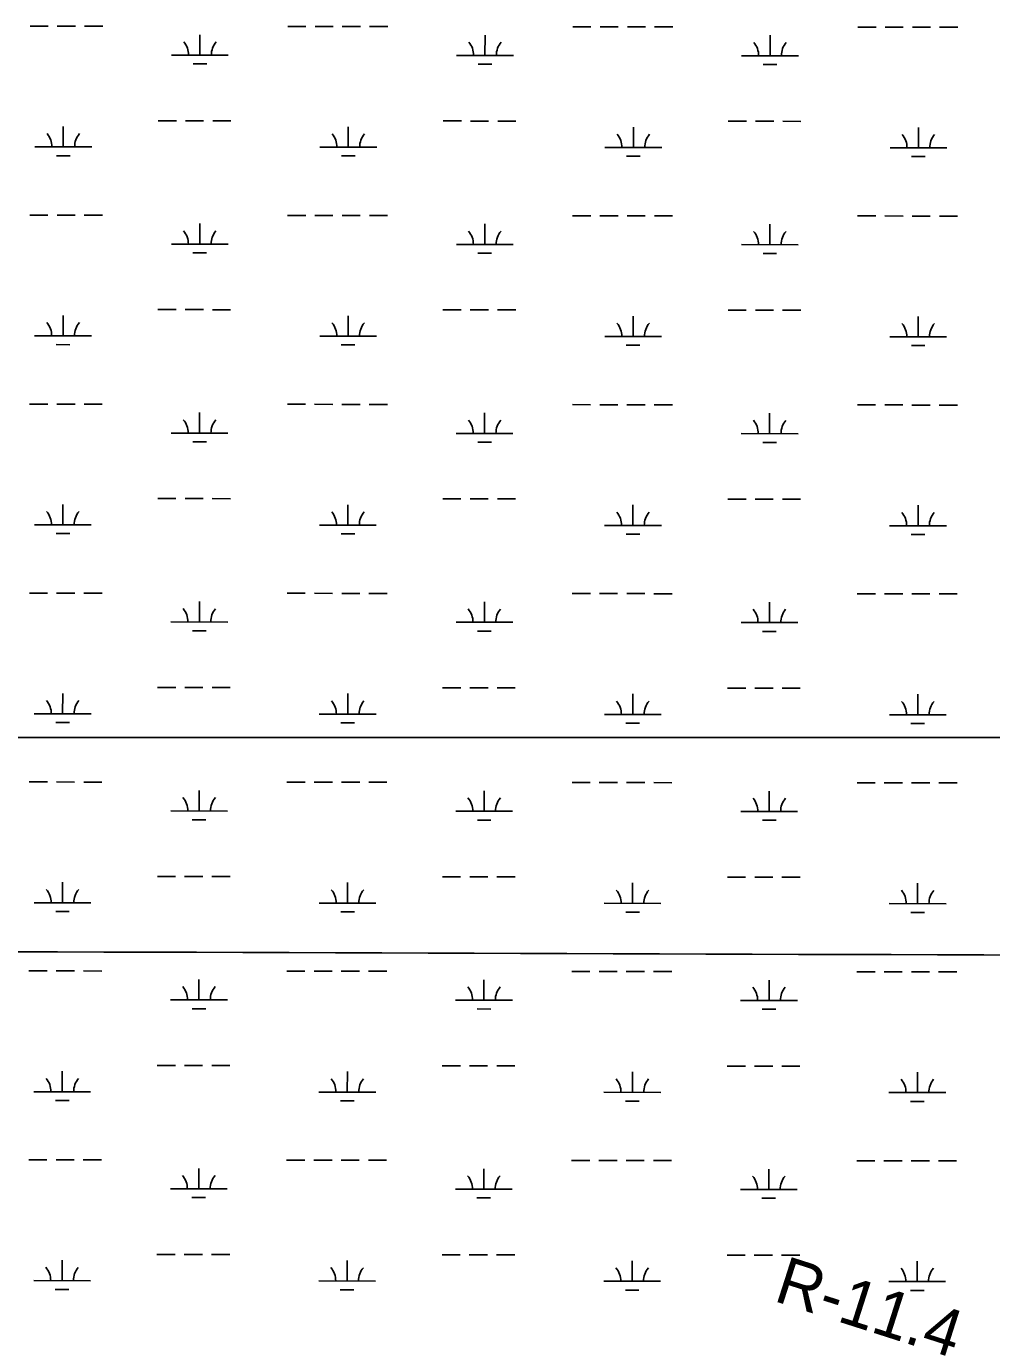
# Model space of a CAD drawing. Extents: x 3148686 to 3186545, y 916144 to 941516.
# Drawn here: x 3158945 to 3160645, y 932988 to 935288 of the extents above; entities that cross this region are included whole.
import ezdxf

# ---------------------------------------------------------------- set-up
doc = ezdxf.new("R2010")
doc.units = 0
for name, color, linetype in [('V-GRID-MAJR', 7, 'Continuous'), ('V-RIVR-RANG-IDEN', 7, 'Continuous'), ('V-SITE-VEGE', 7, 'Continuous'), ('V-WETL-SWMP', 7, 'Continuous')]:
    doc.layers.add(name, color=color, linetype=linetype)

msp = doc.modelspace()

# ---------------------------------------------------------------- linework, layer by layer
at = {"layer": 'V-GRID-MAJR'}
msp.add_spline([(3152965.6, 933679.7), (3155575.1, 933670.5), (3160794.2, 933652.6), (3166013.2, 933635.6), (3171232.3, 933619.2), (3176451.4, 933603.7), (3181670.5, 933588.9), (3184280, 933581.8)], degree=3, dxfattribs=at)
at = {"layer": 'V-SITE-VEGE'}
for p, q in [((3161771.7, 934035.8), (3157650.8, 934035.8)), ((3158561.4, 934035.8), (3161771.7, 934035.8))]:
    msp.add_line(p, q, dxfattribs=at)
at = {"layer": 'V-WETL-SWMP'}
for p, q in [((3158951.7, 935288.4), (3158983.7, 935288.4)), ((3158999.7, 935288.4), (3159031.7, 935288.3)), ((3159047.7, 935288.3), (3159079.7, 935288.3)), ((3159405.6, 935288), (3159437.6, 935287.9)), ((3159453.6, 935287.9), (3159485.6, 935287.9)), ((3159501.6, 935287.9), (3159533.6, 935287.8)), ((3159549.6, 935287.8), (3159581.6, 935287.8)), ((3159907.5, 935287.4), (3159939.5, 935287.4)), ((3159955.5, 935287.4), (3159987.5, 935287.3)), ((3160003.5, 935287.3), (3160035.5, 935287.3)), ((3160051.5, 935287.3), (3160083.5, 935287.2)), ((3160409.4, 935286.9), (3160441.4, 935286.9)), ((3160457.4, 935286.8), (3160489.4, 935286.8)), ((3160505.4, 935286.8), (3160537.4, 935286.8)), ((3160553.4, 935286.7), (3160585.4, 935286.7)), ((3159250.9, 935237.4), (3159251, 935273.4)), ((3159752.8, 935236.8), (3159752.9, 935272.8)), ((3160254.7, 935236.3), (3160254.8, 935272.3)), ((3159200.9, 935237.4), (3159300.9, 935237.3)), ((3159702.8, 935236.9), (3159802.8, 935236.8)), ((3160204.7, 935236.4), (3160304.7, 935236.3)), ((3159238.9, 935222), (3159262.9, 935221.9)), ((3159740.8, 935221.4), (3159764.8, 935221.4)), ((3160242.7, 935220.9), (3160266.7, 935220.9)), ((3159177.4, 935122), (3159209.4, 935122)), ((3159225.4, 935122), (3159257.4, 935121.9)), ((3159273.4, 935121.9), (3159305.4, 935121.9)), ((3159679.3, 935121.5), (3159711.3, 935121.5)), ((3159727.3, 935121.4), (3159759.3, 935121.4)), ((3159775.3, 935121.4), (3159807.3, 935121.4)), ((3160181.2, 935121), (3160213.2, 935120.9)), ((3160229.2, 935120.9), (3160261.2, 935120.9)), ((3160277.2, 935120.9), (3160309.2, 935120.8)), ((3159010.3, 935075.8), (3159010.3, 935111.8)), ((3159512.2, 935075.2), (3159512.2, 935111.2)), ((3160014.1, 935074.7), (3160014.1, 935110.7)), ((3160516, 935074.2), (3160516, 935110.2)), ((3158960.3, 935075.8), (3159060.3, 935075.7)), ((3159462.2, 935075.3), (3159562.2, 935075.2)), ((3159964.1, 935074.8), (3160064.1, 935074.7)), ((3160466, 935074.2), (3160566, 935074.1)), ((3158998.3, 935060.3), (3159022.3, 935060.3)), ((3159500.2, 935059.8), (3159524.2, 935059.8)), ((3160002.1, 935059.3), (3160026.1, 935059.3)), ((3160504, 935058.8), (3160528, 935058.7)), ((3158951.3, 934955.8), (3158983.3, 934955.7)), ((3158999.3, 934955.7), (3159031.3, 934955.7)), ((3159047.3, 934955.7), (3159079.3, 934955.6)), ((3159250.6, 934904.7), (3159250.6, 934940.7)), ((3159405.2, 934955.3), (3159437.2, 934955.2)), ((3159453.2, 934955.2), (3159485.2, 934955.2)), ((3159501.2, 934955.2), (3159533.2, 934955.1)), ((3159549.2, 934955.1), (3159581.2, 934955.1)), ((3159752.5, 934904.2), (3159752.5, 934940.2)), ((3159907.1, 934954.7), (3159939.1, 934954.7)), ((3159955.1, 934954.7), (3159987.1, 934954.7)), ((3160003.1, 934954.6), (3160035.1, 934954.6)), ((3160051.1, 934954.6), (3160083.1, 934954.6)), ((3160254.4, 934903.6), (3160254.4, 934939.6)), ((3160409, 934954.2), (3160441, 934954.2)), ((3160457, 934954.2), (3160489, 934954.1)), ((3160505, 934954.1), (3160537, 934954.1)), ((3160553, 934954.1), (3160585, 934954)), ((3159200.6, 934904.8), (3159300.6, 934904.6)), ((3159702.5, 934904.2), (3159802.5, 934904.1)), ((3160204.4, 934903.7), (3160304.4, 934903.6)), ((3159238.5, 934889.3), (3159262.5, 934889.3)), ((3159740.5, 934888.8), (3159764.5, 934888.7)), ((3160242.4, 934888.2), (3160266.4, 934888.2)), ((3159009.9, 934743.1), (3159010, 934779.1)), ((3159177, 934789.3), (3159209, 934789.3)), ((3159225, 934789.3), (3159257, 934789.3)), ((3159273, 934789.2), (3159305, 934789.2)), ((3159511.8, 934742.6), (3159511.9, 934778.6)), ((3159678.9, 934788.8), (3159710.9, 934788.8)), ((3159726.9, 934788.8), (3159758.9, 934788.7)), ((3159774.9, 934788.7), (3159806.9, 934788.7)), ((3160013.7, 934742), (3160013.8, 934778)), ((3160180.9, 934788.3), (3160212.9, 934788.3)), ((3160228.9, 934788.2), (3160260.9, 934788.2)), ((3160276.9, 934788.2), (3160308.9, 934788.2)), ((3160515.6, 934741.5), (3160515.7, 934777.5)), ((3158959.9, 934743.1), (3159059.9, 934743)), ((3159461.8, 934742.6), (3159561.8, 934742.5)), ((3159963.7, 934742.1), (3160063.7, 934742)), ((3160465.6, 934741.6), (3160565.6, 934741.5)), ((3158997.9, 934727.7), (3159021.9, 934727.6)), ((3159499.8, 934727.1), (3159523.8, 934727.1)), ((3160001.7, 934726.6), (3160025.7, 934726.6)), ((3160503.6, 934726.1), (3160527.6, 934726.1)), ((3158951, 934623.1), (3158983, 934623)), ((3158999, 934623), (3159031, 934623)), ((3159047, 934623), (3159079, 934622.9)), ((3159404.9, 934622.6), (3159436.9, 934622.6)), ((3159452.9, 934622.6), (3159484.9, 934622.5)), ((3159500.9, 934622.5), (3159532.9, 934622.5)), ((3159548.9, 934622.5), (3159580.9, 934622.4)), ((3159906.8, 934622.1), (3159938.8, 934622)), ((3159954.8, 934622), (3159986.8, 934622)), ((3160002.8, 934622), (3160034.8, 934621.9)), ((3160050.8, 934621.9), (3160082.8, 934621.9)), ((3160408.7, 934621.5), (3160440.7, 934621.5)), ((3160456.7, 934621.5), (3160488.7, 934621.5)), ((3160504.7, 934621.4), (3160536.7, 934621.4)), ((3160552.7, 934621.4), (3160584.7, 934621.4)), ((3159250.2, 934572), (3159250.3, 934608)), ((3159752.1, 934571.5), (3159752.2, 934607.5)), ((3160254, 934571), (3160254.1, 934607)), ((3159200.2, 934572.1), (3159300.2, 934572)), ((3159702.1, 934571.5), (3159802.1, 934571.4)), ((3160204, 934571), (3160304, 934570.9)), ((3159238.2, 934556.6), (3159262.2, 934556.6)), ((3159740.1, 934556.1), (3159764.1, 934556.1)), ((3160242, 934555.5), (3160266, 934555.5)), ((3159176.7, 934456.7), (3159208.7, 934456.6)), ((3159224.7, 934456.6), (3159256.7, 934456.6)), ((3159272.7, 934456.6), (3159304.7, 934456.5)), ((3159678.6, 934456.1), (3159710.6, 934456.1)), ((3159726.6, 934456.1), (3159758.6, 934456.1)), ((3159774.6, 934456), (3159806.6, 934456)), ((3160180.5, 934455.6), (3160212.5, 934455.6)), ((3160228.5, 934455.6), (3160260.5, 934455.5)), ((3160276.5, 934455.5), (3160308.5, 934455.5)), ((3159009.6, 934410.4), (3159009.6, 934446.4)), ((3159511.5, 934409.9), (3159511.5, 934445.9)), ((3160013.4, 934409.4), (3160013.4, 934445.4)), ((3160515.3, 934408.8), (3160515.3, 934444.8)), ((3158959.6, 934410.5), (3159059.6, 934410.4)), ((3159461.5, 934409.9), (3159561.5, 934409.8)), ((3159963.4, 934409.4), (3160063.4, 934409.3)), ((3160465.3, 934408.9), (3160565.3, 934408.8)), ((3158997.6, 934395), (3159021.6, 934395)), ((3159499.5, 934394.5), (3159523.5, 934394.4)), ((3160001.4, 934393.9), (3160025.4, 934393.9)), ((3160503.3, 934393.4), (3160527.3, 934393.4)), ((3158950.6, 934290.4), (3158982.6, 934290.4)), ((3158998.6, 934290.4), (3159030.6, 934290.3)), ((3159046.6, 934290.3), (3159078.6, 934290.3)), ((3159249.9, 934239.3), (3159249.9, 934275.3)), ((3159404.5, 934289.9), (3159436.5, 934289.9)), ((3159452.5, 934289.9), (3159484.5, 934289.8)), ((3159500.5, 934289.8), (3159532.5, 934289.8)), ((3159548.5, 934289.8), (3159580.5, 934289.7)), ((3159751.8, 934238.8), (3159751.8, 934274.8)), ((3159906.4, 934289.4), (3159938.4, 934289.4)), ((3159954.4, 934289.3), (3159986.4, 934289.3)), ((3160002.4, 934289.3), (3160034.4, 934289.3)), ((3160050.4, 934289.2), (3160082.4, 934289.2)), ((3160253.7, 934238.3), (3160253.7, 934274.3)), ((3160408.3, 934288.9), (3160440.3, 934288.8)), ((3160456.3, 934288.8), (3160488.3, 934288.8)), ((3160504.3, 934288.8), (3160536.3, 934288.7)), ((3160552.3, 934288.7), (3160584.3, 934288.7)), ((3159199.9, 934239.4), (3159299.9, 934239.3)), ((3159237.8, 934223.9), (3159261.8, 934223.9)), ((3159701.8, 934238.9), (3159801.8, 934238.8)), ((3159739.8, 934223.4), (3159763.8, 934223.4)), ((3160203.7, 934238.3), (3160303.7, 934238.2)), ((3160241.7, 934222.9), (3160265.7, 934222.8)), ((3159009.2, 934077.7), (3159009.3, 934113.7)), ((3159176.3, 934124), (3159208.3, 934124)), ((3159224.3, 934123.9), (3159256.3, 934123.9)), ((3159272.3, 934123.9), (3159304.3, 934123.9)), ((3159511.1, 934077.2), (3159511.2, 934113.2)), ((3159678.2, 934123.5), (3159710.2, 934123.4)), ((3159726.2, 934123.4), (3159758.2, 934123.4)), ((3159774.2, 934123.4), (3159806.2, 934123.3)), ((3160013, 934076.7), (3160013.1, 934112.7)), ((3160180.1, 934122.9), (3160212.1, 934122.9)), ((3160228.1, 934122.9), (3160260.1, 934122.9)), ((3160276.1, 934122.8), (3160308.1, 934122.8)), ((3160514.9, 934076.2), (3160515, 934112.2)), ((3158959.2, 934077.8), (3159059.2, 934077.7)), ((3158997.2, 934062.3), (3159021.2, 934062.3)), ((3159461.1, 934077.3), (3159561.1, 934077.2)), ((3159499.1, 934061.8), (3159523.1, 934061.8)), ((3159963, 934076.7), (3160063, 934076.6)), ((3160001, 934061.3), (3160025, 934061.2)), ((3160464.9, 934076.2), (3160564.9, 934076.1)), ((3160502.9, 934060.7), (3160526.9, 934060.7)), ((3158950.3, 933957.7), (3158982.3, 933957.7)), ((3158998.3, 933957.7), (3159030.3, 933957.6)), ((3159046.3, 933957.6), (3159078.3, 933957.6)), ((3159404.2, 933957.3), (3159436.2, 933957.2)), ((3159452.2, 933957.2), (3159484.2, 933957.2)), ((3159500.2, 933957.2), (3159532.2, 933957.1)), ((3159548.2, 933957.1), (3159580.2, 933957.1)), ((3159906.1, 933956.7), (3159938.1, 933956.7)), ((3159954.1, 933956.7), (3159986.1, 933956.6)), ((3160002.1, 933956.6), (3160034.1, 933956.6)), ((3160050.1, 933956.6), (3160082.1, 933956.5)), ((3160408, 933956.2), (3160440, 933956.2)), ((3160456, 933956.1), (3160488, 933956.1)), ((3160504, 933956.1), (3160536, 933956.1)), ((3160552, 933956), (3160584, 933956)), ((3159249.5, 933906.7), (3159249.6, 933942.7)), ((3159751.4, 933906.1), (3159751.5, 933942.1)), ((3160253.3, 933905.6), (3160253.4, 933941.6)), ((3159199.5, 933906.7), (3159299.5, 933906.6)), ((3159701.4, 933906.2), (3159801.4, 933906.1)), ((3160203.3, 933905.7), (3160303.3, 933905.6)), ((3159237.5, 933891.3), (3159261.5, 933891.2)), ((3159739.4, 933890.7), (3159763.4, 933890.7)), ((3160241.3, 933890.2), (3160265.3, 933890.2)), ((3159176, 933791.3), (3159208, 933791.3)), ((3159224, 933791.3), (3159256, 933791.2)), ((3159272, 933791.2), (3159304, 933791.2)), ((3159677.9, 933790.8), (3159709.9, 933790.8)), ((3159725.9, 933790.7), (3159757.9, 933790.7)), ((3159773.9, 933790.7), (3159805.9, 933790.7)), ((3160179.8, 933790.3), (3160211.8, 933790.2)), ((3160227.8, 933790.2), (3160259.8, 933790.2)), ((3160275.8, 933790.2), (3160307.8, 933790.1)), ((3159008.9, 933745.1), (3159008.9, 933781.1)), ((3159510.8, 933744.5), (3159510.8, 933780.5)), ((3160012.7, 933744), (3160012.7, 933780)), ((3160514.6, 933743.5), (3160514.6, 933779.5)), ((3158958.9, 933745.1), (3159058.9, 933745)), ((3159460.8, 933744.6), (3159560.8, 933744.5)), ((3159962.7, 933744.1), (3160062.7, 933744)), ((3160464.6, 933743.5), (3160564.6, 933743.4)), ((3158996.9, 933729.6), (3159020.9, 933729.6)), ((3159498.8, 933729.1), (3159522.8, 933729.1)), ((3160000.7, 933728.6), (3160024.7, 933728.6)), ((3160502.6, 933728.1), (3160526.6, 933728)), ((3158949.9, 933625.1), (3158981.9, 933625)), ((3158997.9, 933625), (3159029.9, 933625)), ((3159045.9, 933625), (3159077.9, 933624.9)), ((3159403.8, 933624.6), (3159435.8, 933624.5)), ((3159451.8, 933624.5), (3159483.8, 933624.5)), ((3159499.8, 933624.5), (3159531.8, 933624.4)), ((3159547.8, 933624.4), (3159579.8, 933624.4)), ((3159905.7, 933624.1), (3159937.7, 933624)), ((3159249.2, 933574), (3159249.2, 933610)), ((3159751.1, 933573.5), (3159751.1, 933609.5)), ((3159953.7, 933624), (3159985.7, 933624)), ((3160001.7, 933623.9), (3160033.7, 933623.9)), ((3160049.7, 933623.9), (3160081.7, 933623.9)), ((3160253, 933572.9), (3160253, 933608.9)), ((3160407.6, 933623.5), (3160439.6, 933623.5)), ((3160455.6, 933623.5), (3160487.6, 933623.4)), ((3160503.6, 933623.4), (3160535.6, 933623.4)), ((3160551.6, 933623.4), (3160583.6, 933623.3)), ((3159199.2, 933574.1), (3159299.2, 933573.9)), ((3159237.1, 933558.6), (3159261.1, 933558.6)), ((3159701.1, 933573.5), (3159801.1, 933573.4)), ((3159739.1, 933558.1), (3159763.1, 933558)), ((3160203, 933573), (3160303, 933572.9)), ((3160241, 933557.5), (3160265, 933557.5)), ((3159008.5, 933412.4), (3159008.6, 933448.4)), ((3159175.6, 933458.6), (3159207.6, 933458.6)), ((3159223.6, 933458.6), (3159255.6, 933458.6)), ((3159271.6, 933458.5), (3159303.6, 933458.5)), ((3159510.4, 933411.9), (3159510.5, 933447.9)), ((3159677.5, 933458.1), (3159709.5, 933458.1)), ((3159725.5, 933458.1), (3159757.5, 933458)), ((3159773.5, 933458), (3159805.5, 933458)), ((3160012.3, 933411.3), (3160012.4, 933447.3)), ((3160179.4, 933457.6), (3160211.4, 933457.6)), ((3160227.4, 933457.5), (3160259.4, 933457.5)), ((3160275.4, 933457.5), (3160307.4, 933457.5)), ((3160514.2, 933410.8), (3160514.3, 933446.8)), ((3158958.5, 933412.4), (3159058.5, 933412.3)), ((3158996.5, 933397), (3159020.5, 933396.9)), ((3159460.4, 933411.9), (3159560.4, 933411.8)), ((3159498.4, 933396.4), (3159522.4, 933396.4)), ((3159962.3, 933411.4), (3160062.3, 933411.3)), ((3160000.3, 933395.9), (3160024.3, 933395.9)), ((3160464.2, 933410.9), (3160564.2, 933410.8)), ((3160502.2, 933395.4), (3160526.2, 933395.4)), ((3158949.6, 933292.4), (3158981.6, 933292.3)), ((3158997.6, 933292.3), (3159029.6, 933292.3)), ((3159045.6, 933292.3), (3159077.6, 933292.2)), ((3159403.5, 933291.9), (3159435.5, 933291.9)), ((3159451.5, 933291.9), (3159483.5, 933291.8)), ((3159499.5, 933291.8), (3159531.5, 933291.8)), ((3159547.5, 933291.8), (3159579.5, 933291.7)), ((3159905.4, 933291.4), (3159937.4, 933291.3)), ((3159953.4, 933291.3), (3159985.4, 933291.3)), ((3160001.4, 933291.3), (3160033.4, 933291.2)), ((3160049.4, 933291.2), (3160081.4, 933291.2)), ((3160407.3, 933290.8), (3160439.3, 933290.8)), ((3160455.3, 933290.8), (3160487.3, 933290.8)), ((3160503.3, 933290.7), (3160535.3, 933290.7)), ((3160551.3, 933290.7), (3160583.3, 933290.7)), ((3159248.8, 933241.3), (3159248.9, 933277.3)), ((3159750.7, 933240.8), (3159750.8, 933276.8)), ((3160252.6, 933240.3), (3160252.7, 933276.3)), ((3159198.8, 933241.4), (3159298.8, 933241.3)), ((3159700.7, 933240.8), (3159800.7, 933240.7)), ((3160202.6, 933240.3), (3160302.6, 933240.2)), ((3159236.8, 933225.9), (3159260.8, 933225.9)), ((3159738.7, 933225.4), (3159762.7, 933225.4)), ((3160240.6, 933224.8), (3160264.6, 933224.8)), ((3159175.3, 933126), (3159207.3, 933125.9)), ((3159223.3, 933125.9), (3159255.3, 933125.9)), ((3159271.3, 933125.9), (3159303.3, 933125.8)), ((3159677.2, 933125.4), (3159709.2, 933125.4)), ((3159725.2, 933125.4), (3159757.2, 933125.4)), ((3159773.2, 933125.3), (3159805.2, 933125.3)), ((3160179.1, 933124.9), (3160211.1, 933124.9)), ((3160227.1, 933124.9), (3160259.1, 933124.8)), ((3160275.1, 933124.8), (3160307.1, 933124.8)), ((3159008.2, 933079.7), (3159008.2, 933115.7)), ((3159510.1, 933079.2), (3159510.1, 933115.2)), ((3160012, 933078.7), (3160012, 933114.7)), ((3160513.9, 933078.1), (3160513.9, 933114.1)), ((3158958.2, 933079.8), (3159058.2, 933079.7)), ((3159460.1, 933079.2), (3159560.1, 933079.1)), ((3159962, 933078.7), (3160062, 933078.6)), ((3160463.9, 933078.2), (3160563.9, 933078.1)), ((3158996.2, 933064.3), (3159020.2, 933064.3)), ((3159498.1, 933063.8), (3159522.1, 933063.7)), ((3160000, 933063.2), (3160024, 933063.2)), ((3160501.9, 933062.7), (3160525.9, 933062.7))]:
    msp.add_line(p, q, dxfattribs=at)
for centre, start, end in [((3159195.7, 935237.9), 359.1678, 40.7115), ((3159306.2, 935237.8), 139.1678, 180.7115), ((3159697.6, 935237.4), 359.1678, 40.7115), ((3159808.1, 935237.3), 139.1678, 180.7115), ((3160199.5, 935236.8), 359.1678, 40.7115), ((3160310, 935236.7), 139.1678, 180.7115), ((3158955, 935076.3), 359.1678, 40.7115), ((3159065.5, 935076.2), 139.1678, 180.7115), ((3159456.9, 935075.8), 359.1678, 40.7115), ((3159567.4, 935075.7), 139.1678, 180.7115), ((3159958.8, 935075.2), 359.1678, 40.7115), ((3160069.3, 935075.1), 139.1678, 180.7115), ((3160460.8, 935074.7), 359.1678, 40.7115), ((3160571.2, 935074.6), 139.1678, 180.7115), ((3159195.3, 934905.2), 359.1678, 40.7115), ((3159305.8, 934905.1), 139.1678, 180.7115), ((3159697.2, 934904.7), 359.1678, 40.7115), ((3159807.7, 934904.6), 139.1678, 180.7115), ((3160199.1, 934904.2), 359.1678, 40.7115), ((3160309.6, 934904.1), 139.1678, 180.7115), ((3158954.7, 934743.6), 359.1678, 40.7115), ((3159065.2, 934743.5), 139.1678, 180.7115), ((3159456.6, 934743.1), 359.1678, 40.7115), ((3159567.1, 934743), 139.1678, 180.7115), ((3159958.5, 934742.6), 359.1678, 40.7115), ((3160069, 934742.4), 139.1678, 180.7115), ((3160460.4, 934742), 359.1678, 40.7115), ((3160570.9, 934741.9), 139.1678, 180.7115), ((3159195, 934572.6), 359.1678, 40.7115), ((3159305.5, 934572.4), 139.1678, 180.7115), ((3159696.9, 934572), 359.1678, 40.7115), ((3159807.4, 934571.9), 139.1678, 180.7115), ((3160198.8, 934571.5), 359.1678, 40.7115), ((3160309.3, 934571.4), 139.1678, 180.7115), ((3158954.3, 934410.9), 359.1678, 40.7115), ((3159064.8, 934410.8), 139.1678, 180.7115), ((3159456.2, 934410.4), 359.1678, 40.7115), ((3159566.7, 934410.3), 139.1678, 180.7115), ((3159958.1, 934409.9), 359.1678, 40.7115), ((3160068.6, 934409.8), 139.1678, 180.7115), ((3160460.1, 934409.4), 359.1678, 40.7115), ((3160570.5, 934409.2), 139.1678, 180.7115), ((3159194.6, 934239.9), 359.1678, 40.7115), ((3159305.1, 934239.8), 139.1678, 180.7115), ((3159696.5, 934239.4), 359.1678, 40.7115), ((3159807, 934239.2), 139.1678, 180.7115), ((3160198.4, 934238.8), 359.1678, 40.7115), ((3160308.9, 934238.7), 139.1678, 180.7115), ((3158954, 934078.3), 359.1678, 40.7115), ((3159064.5, 934078.2), 139.1678, 180.7115), ((3159455.9, 934077.7), 359.1678, 40.7115), ((3159566.4, 934077.6), 139.1678, 180.7115), ((3159957.8, 934077.2), 359.1678, 40.7115), ((3160068.3, 934077.1), 139.1678, 180.7115), ((3160459.7, 934076.7), 359.1678, 40.7115), ((3160570.2, 934076.6), 139.1678, 180.7115), ((3159194.3, 933907.2), 359.1678, 40.7115), ((3159304.8, 933907.1), 139.1678, 180.7115), ((3159696.2, 933906.7), 359.1678, 40.7115), ((3159806.7, 933906.6), 139.1678, 180.7115), ((3160198.1, 933906.2), 359.1678, 40.7115), ((3160308.6, 933906), 139.1678, 180.7115), ((3158953.6, 933745.6), 359.1678, 40.7115), ((3159064.1, 933745.5), 139.1678, 180.7115), ((3159455.5, 933745.1), 359.1678, 40.7115), ((3159566, 933745), 139.1678, 180.7115), ((3159957.4, 933744.5), 359.1678, 40.7115), ((3160067.9, 933744.4), 139.1678, 180.7115), ((3160459.4, 933744), 359.1678, 40.7115), ((3160569.8, 933743.9), 139.1678, 180.7115), ((3159193.9, 933574.5), 359.1678, 40.7115), ((3159304.4, 933574.4), 139.1678, 180.7115), ((3159695.8, 933574), 359.1678, 40.7115), ((3159806.3, 933573.9), 139.1678, 180.7115), ((3160197.7, 933573.5), 359.1678, 40.7115), ((3160308.2, 933573.4), 139.1678, 180.7115), ((3158953.3, 933412.9), 359.1678, 40.7115), ((3159063.8, 933412.8), 139.1678, 180.7115), ((3159455.2, 933412.4), 359.1678, 40.7115), ((3159565.7, 933412.3), 139.1678, 180.7115), ((3159957.1, 933411.9), 359.1678, 40.7115), ((3160067.6, 933411.8), 139.1678, 180.7115), ((3160459, 933411.3), 359.1678, 40.7115), ((3160569.5, 933411.2), 139.1678, 180.7115), ((3159193.6, 933241.9), 359.1678, 40.7115), ((3159304.1, 933241.7), 139.1678, 180.7115), ((3159695.5, 933241.3), 359.1678, 40.7115), ((3159806, 933241.2), 139.1678, 180.7115), ((3160197.4, 933240.8), 359.1678, 40.7115), ((3160307.9, 933240.7), 139.1678, 180.7115), ((3158952.9, 933080.3), 359.1678, 40.7115), ((3159063.4, 933080.1), 139.1678, 180.7115), ((3159454.8, 933079.7), 359.1678, 40.7115), ((3159565.3, 933079.6), 139.1678, 180.7115), ((3159956.7, 933079.2), 359.1678, 40.7115), ((3160067.2, 933079.1), 139.1678, 180.7115), ((3160458.7, 933078.7), 359.1678, 40.7115), ((3160569.1, 933078.5), 139.1678, 180.7115)]:
    msp.add_arc(centre, 35.2, start, end, dxfattribs=at)

# ---------------------------------------------------------------- texts
at = {"layer": 'V-RIVR-RANG-IDEN'}
msp.add_text('R-11.4', height=83, rotation=342.2798, dxfattribs=at).set_placement((3160259.1, 933044.7))

doc.saveas('drawing.dxf')
